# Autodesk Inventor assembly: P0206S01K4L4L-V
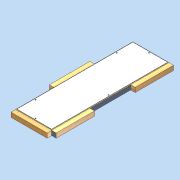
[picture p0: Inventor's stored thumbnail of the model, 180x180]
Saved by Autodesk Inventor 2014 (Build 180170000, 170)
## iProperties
Created: 2011-04
Part Number: P0206S01K4L4L-V
Document SubType Name: Assembly
Designer: david.appleford
Description: 0.5w x 1.5w 01 Panel - 5 Locks 4 Lugs LH
Mass: 22000 g
Surface Area: 29419.9 cm^2
Volume: 86479.4 cm^3
Density: 0.254396 g/cm^3
Cost Center: £93.00
Justset: False
Author: david.appleford
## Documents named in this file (5)
- C:\Documents and Settings\john.everitt\Local Settings\My Documents\Vault\Production MkII\VIRTUAL ELEMENTS\Virtual Walls\Virtual Timber + MgO\P0206S01K5L4L-V.iam
- C:\Documents and Settings\john.everitt\Local Settings\My Documents\Vault\Production MkII\Virtual Elements\LA02M3.ipt
- C:\Documents and Settings\john.everitt\Local Settings\My Documents\Vault\Production MkII\Virtual Elements\LA02E3.ipt
- C:\Documents and Settings\john.everitt\Local Settings\My Documents\Vault\Production MkII\VIRTUAL ELEMENTS\Virtual Lugs\Superceded Lugs\LA02C3V.ipt
- C:\Documents and Settings\john.everitt\Local Settings\My Documents\Vault\Production MkII\VIRTUAL ELEMENTS\Virtual Walls\Virtual Timber + MgO\P0206S01K5-V.ipt
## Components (5 placed, 4 different names)
1. P0206S01K5-V:1 — Mate:2, Flush:3, Flush:4, Mate:5, Flush:10, Mate:6, Flush:11, Mate:7, Mate:8, Flush:12, Flush:13
2. LA02E3:1 — Mate:2, Flush:3, Flush:4
3. LA02M3:2 — Mate:5, Flush:10
4. LA02C3V:1 — Mate:6, Flush:11, Mate:7
5. LA02C3V:2 — Mate:8, Flush:12, Flush:13
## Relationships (11: Flush 6, Mate 5)
- Mate:2: P0206S01K5-V:1 ↔ LA02E3:1
- Flush:3: P0206S01K5-V:1 ↔ LA02E3:1
- Flush:4: P0206S01K5-V:1 ↔ LA02E3:1
- Mate:5: P0206S01K5-V:1 ↔ LA02M3:2
- Flush:10: P0206S01K5-V:1 ↔ LA02M3:2
- Mate:6: P0206S01K5-V:1 ↔ LA02C3V:1
- Flush:11: P0206S01K5-V:1 ↔ LA02C3V:1
- Mate:7: P0206S01K5-V:1 ↔ LA02C3V:1
- Mate:8: P0206S01K5-V:1 ↔ LA02C3V:2
- Flush:12: P0206S01K5-V:1 ↔ LA02C3V:2
- Flush:13: P0206S01K5-V:1 ↔ LA02C3V:2
## Named parameters: t = 1 mm, Cl = 2 mm
